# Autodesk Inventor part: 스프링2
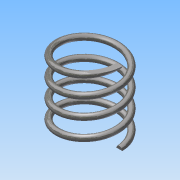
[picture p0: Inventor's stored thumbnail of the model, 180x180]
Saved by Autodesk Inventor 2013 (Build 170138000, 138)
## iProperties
Created: 2016-07
Part Number: 스프링2
Material: 스테인리스강
Document SubType Name: Modeling
Designer: Administrator
Mass: 6.2731 g
Surface Area: 15.7615 cm^2
Volume: 0.776373 cm^3
Density: 8.08 g/cm^3
Author: Administrator
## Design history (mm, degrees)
sketch "스케치1"
  geometry: L1 (0, 0)-(10, 0); L2 (10, 0)-(10, 25); L3 (10, 25)-(0, 25); L4 (0, 25)-(0, 0); C1 r 1 at (10, 25)
  constraints: 8 end point, 2 parallel, 1 centre point, 1 coincident, 1 horizontal, 1 perpendicular
  dimensions: "d0" = 20 diameter of L2 L4; "d2" = 25 distance between parallel lines of L1 L3 (derived); "d3" = 2 diameter of C1
feature "코일1" sketch "스케치1" pitch "d4" = 10; turns "d6" = 4; dims "d5" = 25 (= d2), "d7" = 0, angle "d8" = 90 deg, angle "d9" = 90 deg, "d10" = 0, "d11" = 0
feature "분할1"
node "작업 평면1"
feature "분할2"
node "솔리드1"
other parameters: "d12" = 25
